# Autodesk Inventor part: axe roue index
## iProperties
Author: Administrateur
Created: 2001-04
Part Number: axe roue index
Material: Par défaut
Document SubType Name: Modélisation
Designer: Administrateur
Control State: 0
Master: False
Checked Out: False
PropertySet Name: Design Tracking Control
Shininess: 20.0
PropertySet Name: _Private Model Information
Length Units: 11269
Angle Units: 11283
Time Units: 11279
Mass Units: 11290
Length Display Precision: 3
Angle Display Precision: 2
Compacted: False
Density: 0.0
Volumn: 0.0
Area: 0.0
PropertySet Name: Model Information
